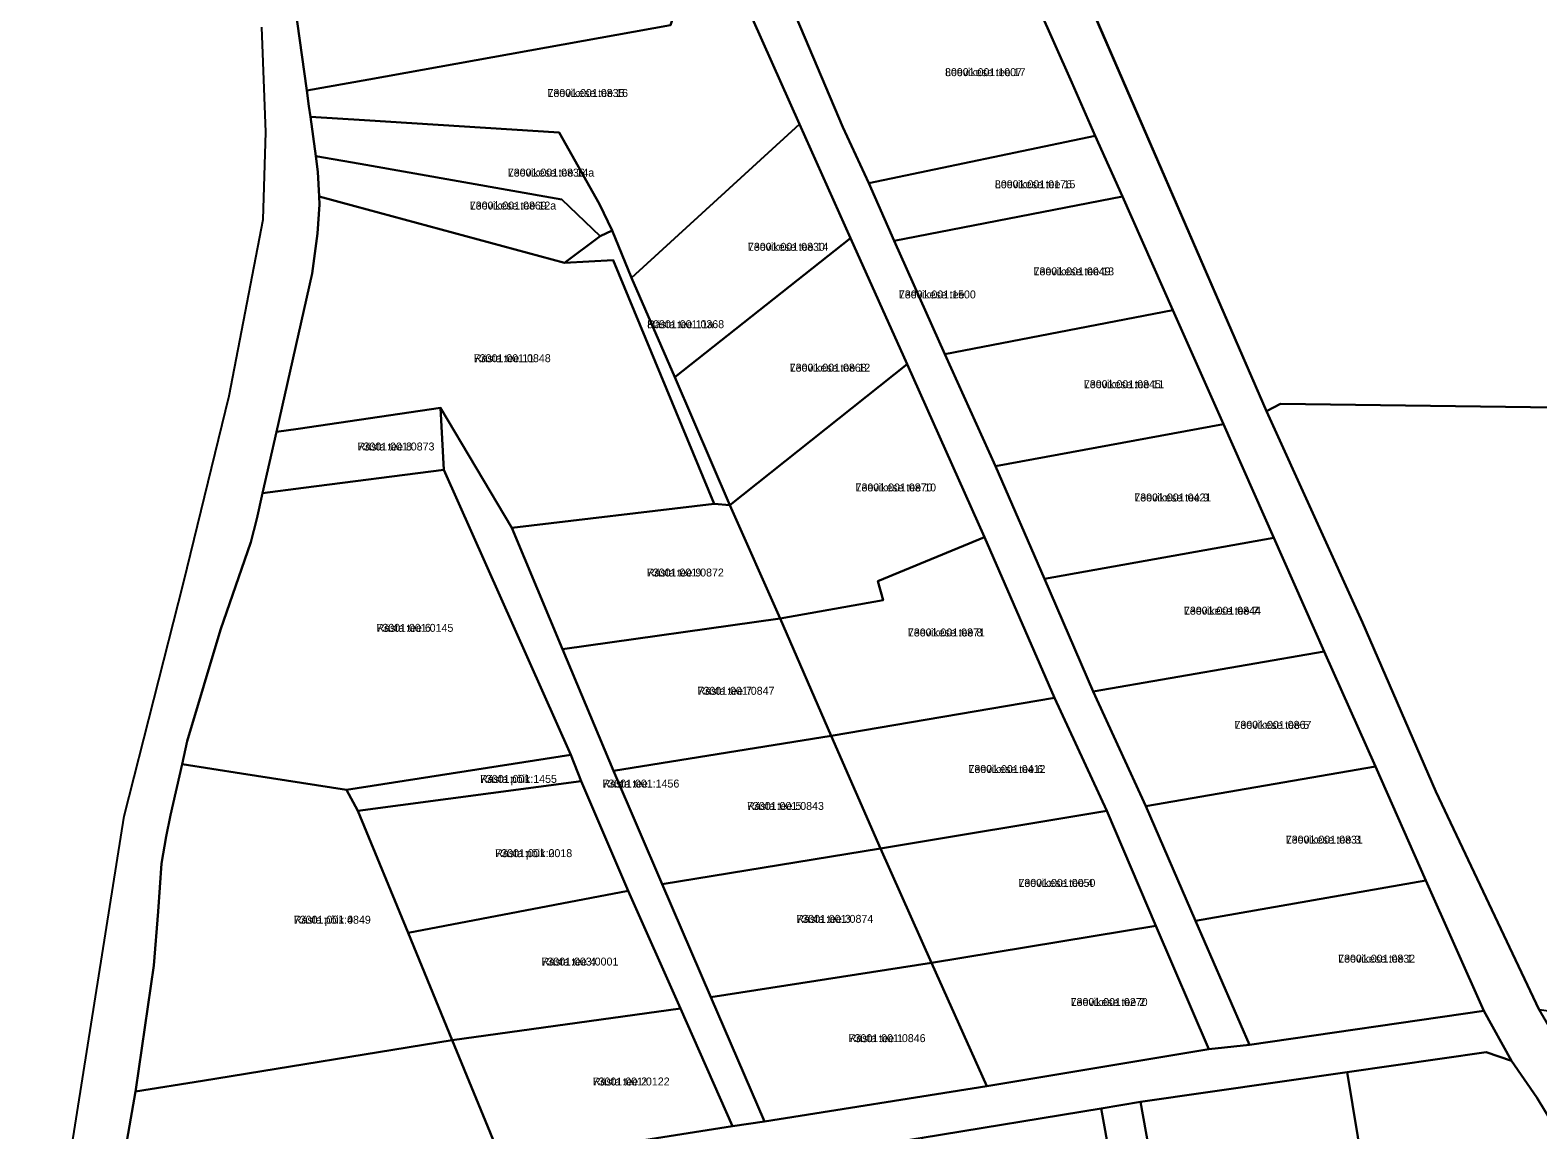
# Model space of a CAD drawing. Extents: x 524000 to 564260, y 6469338 to 6496391.
# Drawn here: x 525763.1 to 526047.3, y 6476132.3 to 6476339.7 of the extents above; entities that cross this region are included whole.
import ezdxf

# ---------------------------------------------------------------- set-up
doc = ezdxf.new("R2010")
doc.units = 0
for name, color, linetype in [('L_AADRESS', 7, 'Continuous'), ('PIIR', 7, 'Continuous'), ('TUNNUS', 7, 'Continuous')]:
    doc.layers.add(name, color=color, linetype=linetype)

msp = doc.modelspace()

# ---------------------------------------------------------------- linework, layer by layer
at = {"layer": 'PIIR'}
for points in [[(525996.17, 6476267.86), (525950.74, 6476372.46), (525953.47, 6476373.66), (525958.34, 6476372.6), (526025.41, 6476357.92), (526128.94, 6476335.28), (526102.38, 6476267.82), (525998.79, 6476269.25)], [(525812.41, 6476350.46), (525838.07, 6476355.05), (525889.22, 6476364.21), (525890.65, 6476361.18), (525883.85, 6476340.62), (525826.95, 6476330.4), (525815.27, 6476328.3), (525812.6, 6476347.68)], [(525876.47, 6476292.98), (525872.86, 6476301.88), (525870.47, 6476306.84), (525862.84, 6476320.41), (525826.13, 6476322.7), (525815.95, 6476323.34), (525815.68, 6476325.33), (525815.27, 6476328.3), (525826.95, 6476330.4), (525883.85, 6476340.62), (525890.65, 6476361.18), (525908.16, 6476321.93)], [(525921.21, 6476310.82), (525916.34, 6476321.39), (525906.68, 6476344.08), (525950, 6476351.19), (525959.44, 6476329.78), (525963.89, 6476319.75)], [(526375.73, 6476296.77), (526378.53, 6476185.04), (526338.66, 6476182.78), (526339.55, 6476132.93), (526051.02, 6476154.48), (526047.57, 6476155), (526028.06, 6476196.11), (526014.24, 6476228.01), (525996.17, 6476267.86), (525998.79, 6476269.25), (526102.38, 6476267.82), (526128.94, 6476335.28)], [(525825.35, 6476314.45), (525816.97, 6476315.93), (525815.95, 6476323.34), (525826.13, 6476322.7), (525862.84, 6476320.41), (525870.47, 6476306.84), (525872.86, 6476301.88), (525870.59, 6476300.81), (525863.35, 6476307.75)], [(525876.47, 6476292.98), (525908.16, 6476321.93), (525917.78, 6476300.44), (525884.65, 6476274.23)], [(525926.01, 6476299.98), (525921.21, 6476310.82), (525963.89, 6476319.75), (525969, 6476308.34)], [(525817.62, 6476308.31), (525817.38, 6476312.96), (525816.97, 6476315.93), (525825.35, 6476314.45), (525863.35, 6476307.75), (525870.59, 6476300.81), (525863.86, 6476295.78), (525824.33, 6476306.49)], [(525813.63, 6476264.52), (525809.55, 6476263.92), (525816.31, 6476293.81), (525817.27, 6476301.32), (525817.69, 6476306.82), (525817.62, 6476308.31), (525824.33, 6476306.49), (525863.86, 6476295.78), (525873, 6476296.29), (525892.06, 6476250.39), (525853.93, 6476245.86), (525840.46, 6476268.5)], [(525926.01, 6476299.98), (525969, 6476308.34), (525978.53, 6476286.86), (525935.55, 6476278.56)], [(525872.86, 6476301.88), (525876.47, 6476292.98), (525884.65, 6476274.23), (525895.01, 6476250.13), (525892.06, 6476250.39), (525873, 6476296.29), (525863.86, 6476295.78), (525870.59, 6476300.81)], [(525884.65, 6476274.23), (525917.78, 6476300.44), (525928.41, 6476276.71), (525895.01, 6476250.13)], [(525935.55, 6476278.56), (525978.53, 6476286.86), (525988.04, 6476265.42), (525945.1, 6476257.49)], [(525895.01, 6476250.13), (525928.41, 6476276.71), (525943.03, 6476244.09), (525922.88, 6476235.79), (525923.9, 6476232.18), (525904.51, 6476228.72)], [(525806.94, 6476252.36), (525809.55, 6476263.92), (525813.63, 6476264.52), (525840.46, 6476268.5), (525841.13, 6476256.78), (525814.68, 6476253.36)], [(525865.04, 6476203.04), (525841.13, 6476256.78), (525840.46, 6476268.5), (525853.93, 6476245.86), (525863.5, 6476222.94), (525873.07, 6476200.01), (525882.25, 6476178.67), (525891.44, 6476157.33), (525901.52, 6476133.91), (525895.5, 6476133.01), (525885.7, 6476155.21), (525875.88, 6476177.38), (525867, 6476198.06)], [(525988.04, 6476265.42), (525997.55, 6476243.98), (525954.29, 6476236.22), (525945.1, 6476257.49)], [(525802.95, 6476199.53), (525791.76, 6476201.26), (525792.73, 6476205.6), (525799.04, 6476226.61), (525804.76, 6476243.12), (525805.85, 6476247.55), (525806.94, 6476252.36), (525814.68, 6476253.36), (525841.13, 6476256.78), (525865.04, 6476203.04), (525822.74, 6476196.47)], [(525853.93, 6476245.86), (525892.06, 6476250.39), (525895.01, 6476250.13), (525904.51, 6476228.72), (525863.5, 6476222.94)], [(525904.51, 6476228.72), (525923.9, 6476232.18), (525922.88, 6476235.79), (525943.03, 6476244.09), (525956.2, 6476213.82), (525914.13, 6476206.65)], [(525954.29, 6476236.22), (525997.55, 6476243.98), (526007.06, 6476222.54), (525963.48, 6476214.96)], [(525863.5, 6476222.94), (525904.51, 6476228.72), (525914.13, 6476206.65), (525873.07, 6476200.01)], [(525963.48, 6476214.96), (526007.06, 6476222.54), (526016.68, 6476200.86), (525973.39, 6476193.36)], [(525956.2, 6476213.82), (525966.08, 6476192.47), (525923.42, 6476185.41), (525914.13, 6476206.65)], [(525873.07, 6476200.01), (525914.13, 6476206.65), (525923.42, 6476185.41), (525882.25, 6476178.67)], [(525824.87, 6476192.49), (525822.74, 6476196.47), (525865.04, 6476203.04), (525867, 6476198.06)], [(525783.01, 6476139.56), (525783.08, 6476139.96), (525786.43, 6476163.32), (525787.28, 6476173.48), (525787.91, 6476182.58), (525788.76, 6476187.67), (525789.61, 6476191.69), (525791.76, 6476201.26), (525802.95, 6476199.53), (525822.74, 6476196.47), (525824.87, 6476192.49), (525834.36, 6476169.47), (525842.68, 6476149.27), (525795.63, 6476141.61)], [(525973.39, 6476193.36), (526016.68, 6476200.86), (526026.22, 6476179.36), (525982.8, 6476171.76)], [(525824.87, 6476192.49), (525867, 6476198.06), (525875.88, 6476177.38), (525834.36, 6476169.47)], [(525923.42, 6476185.41), (525966.08, 6476192.47), (525975.28, 6476170.83), (525933.05, 6476163.84)], [(525882.25, 6476178.67), (525923.42, 6476185.41), (525933.05, 6476163.84), (525891.44, 6476157.33)], [(525834.36, 6476169.47), (525875.88, 6476177.38), (525885.7, 6476155.21), (525842.68, 6476149.27)], [(525982.8, 6476171.76), (526026.22, 6476179.36), (526037.12, 6476154.81), (525992.98, 6476148.38)], [(525933.05, 6476163.84), (525975.28, 6476170.83), (525985.32, 6476147.57), (525943.44, 6476140.56)], [(525891.44, 6476157.33), (525933.05, 6476163.84), (525943.44, 6476140.56), (525901.52, 6476133.91)], [(525802.67, 6476109.82), (525780.39, 6476106.14), (525776.7, 6476105.53), (525777.46, 6476109.37), (525795.3, 6476112.67), (525807.85, 6476119.23), (525852.19, 6476126.2), (525895.5, 6476133.01), (525901.52, 6476133.91), (525943.44, 6476140.56), (525985.32, 6476147.57), (525992.98, 6476148.38), (526037.12, 6476154.81), (526042.32, 6476145.38), (526037.59, 6476146.99), (526011.36, 6476143.22), (525972.4, 6476137.61), (525965, 6476136.39), (525931.24, 6476130.86), (525896.76, 6476125.22), (525889.47, 6476124.03), (525848.09, 6476117.25), (525809.7, 6476110.97)], [(525842.68, 6476149.27), (525885.7, 6476155.21), (525895.5, 6476133.01), (525852.19, 6476126.2)], [(525783.01, 6476139.56), (525795.63, 6476141.61), (525842.68, 6476149.27), (525852.19, 6476126.2), (525807.85, 6476119.23), (525795.3, 6476112.67), (525777.46, 6476109.37), (525779.6, 6476120.16)], [(526015.36, 6476118.86), (526011.36, 6476143.22), (526037.59, 6476146.99), (526042.32, 6476145.38), (526047.11, 6476138.45), (526061.14, 6476115.23), (526020.58, 6476107.92)], [(525972.4, 6476137.61), (526011.36, 6476143.22), (526015.36, 6476118.86), (525977, 6476112.09)], [(525970.06, 6476108.29), (525965, 6476136.39), (525972.4, 6476137.61), (525977, 6476112.09), (525981.2, 6476089.76), (525985.16, 6476066.79), (525989.12, 6476044.78), (525993.24, 6476022.37), (525996.88, 6475999.89), (525989.74, 6475999.15), (525983.69, 6476032.57), (525978.76, 6476059.98)], [(525931.24, 6476130.86), (525965, 6476136.39), (525970.06, 6476108.29), (525932.64, 6476102.95)]]:
    msp.add_lwpolyline(points, close=True, dxfattribs=at)
for points in [[(525950.8, 6476372.5), (525996.17, 6476267.86), (526014.24, 6476228.01), (526028.06, 6476196.11), (526047.57, 6476155), (526123.12, 6476025.35), (526134.42, 6476005.42), (526143.63, 6475992.6), (526159.4, 6475993.26), (526301.69, 6475999.74)], [(525906.68, 6476344.08), (525916.34, 6476321.39), (525921.21, 6476310.82), (525926.01, 6476299.98), (525935.55, 6476278.56), (525945.1, 6476257.49), (525954.29, 6476236.22), (525963.48, 6476214.96), (525973.39, 6476193.36), (525982.8, 6476171.76), (525992.98, 6476148.38), (525985.32, 6476147.57), (525975.28, 6476170.83), (525966.08, 6476192.47), (525956.2, 6476213.82), (525943.03, 6476244.09), (525928.41, 6476276.71), (525917.78, 6476300.44), (525908.16, 6476321.93), (525890.65, 6476361.18)], [(526256.06, 6475983.6), (526134.7, 6475978.52), (526128.32, 6475994.39), (526119.53, 6476012.27), (526116.81, 6476017.8), (526105.17, 6476041), (526091.93, 6476064.84), (526076.93, 6476089.68), (526061.14, 6476115.23), (526047.11, 6476138.45), (526042.32, 6476145.38), (526037.12, 6476154.81), (526026.22, 6476179.36), (526016.68, 6476200.86), (526007.06, 6476222.54), (525997.55, 6476243.98), (525988.04, 6476265.42), (525978.53, 6476286.86), (525969, 6476308.34), (525963.89, 6476319.75), (525959.44, 6476329.78), (525950, 6476351.19)], [(525812.6, 6476347.68), (525815.27, 6476328.3), (525815.68, 6476325.33), (525815.95, 6476323.34), (525816.97, 6476315.93), (525817.38, 6476312.96), (525817.62, 6476308.31), (525817.69, 6476306.82), (525817.27, 6476301.32), (525816.31, 6476293.81), (525809.55, 6476263.92), (525806.94, 6476252.36), (525805.85, 6476247.55), (525804.76, 6476243.12), (525799.04, 6476226.61), (525792.73, 6476205.6), (525791.76, 6476201.26), (525789.61, 6476191.69), (525788.76, 6476187.67), (525787.91, 6476182.58), (525787.28, 6476173.48), (525786.43, 6476163.32), (525783.08, 6476139.96), (525783.01, 6476139.56), (525779.6, 6476120.16)], [(525852.01, 6475922.02), (525842.13, 6475932.97), (525836.68, 6475939.16), (525804.56, 6475968.82), (525787.27, 6475989.67), (525774.91, 6476009.12), (525768.98, 6476023.49), (525765.52, 6476039.24), (525763.88, 6476060.43), (525763.14, 6476075.92), (525765.03, 6476092.52), (525766.62, 6476101.47), (525774.04, 6476148.29), (525780.87, 6476191.47), (525792.05, 6476235.46), (525800.68, 6476270.72), (525807.04, 6476303.95), (525807.55, 6476320.43), (525806.79, 6476340.22)]]:
    msp.add_lwpolyline(points, dxfattribs=at)

# ---------------------------------------------------------------- texts
at = {"layer": 'L_AADRESS'}
for s, p in [('Leevikese tee 17', (525935.57, 6476331.01)), ('Leevikese tee 16', (525860.65, 6476327.08)), ('Leevikese tee 14a', (525853.17, 6476312.07)), ('Leevikese tee 15', (525944.97, 6476309.87)), ('Leevikese tee 12a', (525846, 6476305.86)), ('Leevikese tee 14', (525898.42, 6476298.08)), ('Leevikese tee 13', (525952.26, 6476293.45)), ('Leevikese tee', (525926.87, 6476289.1)), ('Rästa tee 11a', (525879.43, 6476283.49)), ('Rästa tee 11', (525846.75, 6476277.08)), ('Leevikese tee 12', (525906.3, 6476275.29)), ('Leevikese tee 11', (525961.74, 6476272.17)), ('Rästa tee 8', (525824.84, 6476260.43)), ('Leevikese tee 10', (525918.71, 6476252.71)), ('Leevikese tee 9', (525971.25, 6476250.82)), ('Rästa tee 9', (525879.38, 6476236.67)), ('Leevikese tee 7', (525980.6, 6476229.47)), ('Rästa tee 6', (525828.4, 6476226.24)), ('Leevikese tee 8', (525928.57, 6476225.37)), ('Rästa tee 7', (525888.92, 6476214.37)), ('Leevikese tee 5', (525990.12, 6476207.95)), ('Leevikese tee 6', (525939.99, 6476199.62)), ('Rästa põik', (525847.92, 6476197.76)), ('Rästa tee', (525870.99, 6476196.88)), ('Rästa tee 5', (525898.24, 6476192.66)), ('Leevikese tee 3', (525999.8, 6476186.31)), ('Rästa põik 2', (525850.8, 6476183.76)), ('Leevikese tee 4', (525949.41, 6476178.15)), ('Rästa põik 4', (525812.84, 6476171.21)), ('Rästa tee 3', (525907.54, 6476171.37)), ('Rästa tee 4', (525859.5, 6476163.32)), ('Leevikese tee 1', (526009.67, 6476163.87)), ('Leevikese tee 2', (525959.25, 6476155.69)), ('Rästa tee 1', (525917.4, 6476148.88)), ('Rästa tee 2', (525869.16, 6476140.71))]:
    msp.add_text(s, height=1.5, dxfattribs=at).set_placement(p)
at = {"layer": 'TUNNUS'}
for s, p in [('80901:001:1007', (525935.57, 6476331.01)), ('73001:001:0835', (525860.65, 6476327.08)), ('73001:001:0836', (525853.17, 6476312.07)), ('80901:001:0176', (525944.97, 6476309.87)), ('73001:001:0869', (525846, 6476305.86)), ('73001:001:0830', (525898.42, 6476298.08)), ('73001:001:0049', (525952.26, 6476293.45)), ('73001:001:1500', (525926.87, 6476289.1)), ('80901:001:0368', (525879.43, 6476283.49)), ('73001:001:0848', (525846.75, 6476277.08)), ('73001:001:0868', (525906.3, 6476275.29)), ('73001:001:0845', (525961.74, 6476272.17)), ('73001:001:0873', (525824.84, 6476260.43)), ('73001:001:0870', (525918.71, 6476252.71)), ('73001:001:0421', (525971.25, 6476250.82)), ('73001:001:0872', (525879.38, 6476236.67)), ('73001:001:0844', (525980.6, 6476229.47)), ('73001:001:0145', (525828.4, 6476226.24)), ('73001:001:0871', (525928.57, 6476225.37)), ('73001:001:0847', (525888.92, 6476214.37)), ('73001:001:0867', (525990.12, 6476207.95)), ('73001:001:0412', (525939.99, 6476199.62)), ('73001:001:1455', (525847.92, 6476197.76)), ('73001:001:1456', (525870.99, 6476196.88)), ('73001:001:0843', (525898.24, 6476192.66)), ('73001:001:0831', (525999.8, 6476186.31)), ('73001:001:0018', (525850.8, 6476183.76)), ('73001:001:0050', (525949.41, 6476178.15)), ('73001:001:0849', (525812.84, 6476171.21)), ('73001:001:0874', (525907.54, 6476171.37)), ('73001:003:0001', (525859.5, 6476163.32)), ('73001:001:0832', (526009.67, 6476163.87)), ('73001:001:0270', (525959.25, 6476155.69)), ('73001:001:0846', (525917.4, 6476148.88)), ('73001:001:0122', (525869.16, 6476140.71))]:
    msp.add_text(s, height=1.5, dxfattribs=at).set_placement(p)

doc.saveas('drawing.dxf')
